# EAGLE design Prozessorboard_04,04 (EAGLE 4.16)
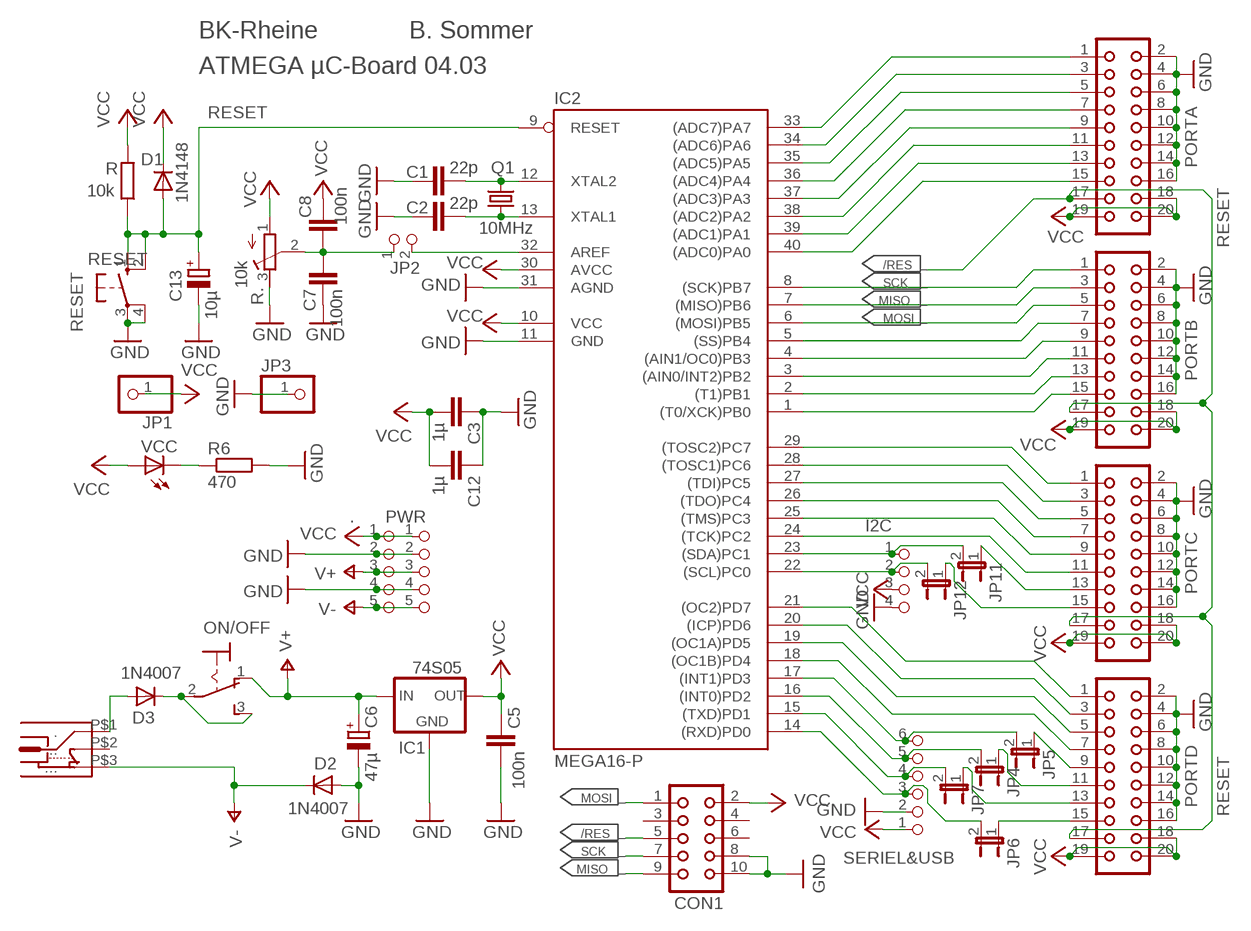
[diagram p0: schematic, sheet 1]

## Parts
.  PINHD-1X5  [1X05]
C1  22p  C-EU050-030X075  [C050-030X075]
C2  22p  C-EU050-030X075  [C050-030X075]
C3  1µ  C-EU025-030X050  [C025-030X050]
C5  100n  C-EU025-025X050  [C025-025X050]
C6  47µ  CPOL-EUE5-8.5  [E5-8,5]
C7  100n  C-EU025-030X050  [C025-030X050]
C8  100n  C-EU025-030X050  [C025-030X050]
C12  1µ  C-EU025-030X050  [C025-030X050]
C13  10µ  CPOL-EUE2.5-7  [E2,5-7]
CON1  CON10  [CON10]
D1  1N4148  DIODE-D-7.5  [D-7.5]
D2  1N4007  DIODE-D-7.5  [D-7.5]
D3  1N4007  DIODE-D-7.5  [D-7.5]
I2C  PINHD-1X4  [1X04]
IC1  74S05  78XXS  [78XXS]
IC2  MEGA16-P  [DIL40]
JP1  PINHD-1X1  [1X01]
JP2  PINHD-1X2  [1X02]
JP3  PINHD-1X1  [1X01]
JP4  JP1E  [JP1]
JP5  JP1E  [JP1]
JP6  JP1E  [JP1]
JP7  JP1E  [JP1]
JP11  JP1E  [JP1]
JP12  JP1E  [JP1]
ON/OFF  320-916  [320-916]
PORTA  CON20  [CON20]
PORTB  CON20  [CON20]
PORTC  CON20  [CON20]
PORTD  CON20  [CON20]
PWR  PINHD-1X5  [1X05]
Q1  10MHz  CRYTALHC49U70  [HC49U70]
R  10k  R-EU_0204/7  [0204/7]
R6  470  R-EU_0204/7  [0204/7]
R.  10k  R-TRIMM64Y  [RTRIM64Y]
RESET  10-XX  [B3F-10XX]
SERIEL&USB  PINHD-1X6  [1X06]
U$1  DC-CONNECTOR  [DC-CONNECTOR]
VCC  LED3MM  [LED3MM]

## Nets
AREF: IC2.32(AREF) JP2.2
AREF/P: C7.2 C8.1 JP2.1 R..2(S)
GND: ..2 ..4 C1.1 C2.1 C3.1 C5.1 C6.- C7.1 C12.1 C13.- CON1.8 CON1.10 D2.A I2C.4 IC1.GND IC2.11(GND) IC2.31(AGND) JP3.1 PORTA.2 PORTA.4 PORTA.6 PORTA.8 PORTA.10 PORTA.12 PORTA.14 PORTA.16 PORTB.2 PORTB.4 PORTB.6 PORTB.8 PORTB.10 PORTB.12 PORTB.14 PORTB.16 PORTC.2 PORTC.4 PORTC.6 PORTC.8 PORTC.10 PORTC.12 PORTC.14 PORTC.16 PORTD.2 PORTD.4 PORTD.6 PORTD.8 PORTD.10 PORTD.12 PORTD.14 PORTD.16 PWR.2 PWR.4 R6.2 R..3(A) RESET.3(P) RESET.4(P1) SERIEL&USB.2
N$2: D3.A U$1.P$1(.)
N$9: JP11.1 PORTC.13
N$16: R6.1 VCC.K(C)
N$21: I2C.2 IC2.22((SCL)PC0) JP12.2
N$23: D3.C ON/OFF.2(P) ON/OFF.3(S)
N$26: JP5.1 PORTD.9
N$27: JP4.1 PORTD.11
N$29: JP7.1 PORTD.13
N$30: JP6.1 PORTD.15
PA0: IC2.40((ADC0)PA0) PORTA.15
PA1: IC2.39((ADC1)PA1) PORTA.13
PA2: IC2.38((ADC2)PA2) PORTA.11
PA3: IC2.37((ADC3)PA3) PORTA.9
PA4: IC2.36((ADC4)PA4) PORTA.7
PA5: IC2.35((ADC5)PA5) PORTA.5
PA6: IC2.34((ADC6)PA6) PORTA.3
PA7: IC2.33((ADC7)PA7) PORTA.1
PB0: IC2.1((T0/XCK)PB0) PORTB.15
PB1: IC2.2((T1)PB1) PORTB.13
PB2: IC2.3((AIN0/INT2)PB2) PORTB.11
PB3: IC2.4((AIN1/OC0)PB3) PORTB.9
PB4: IC2.5((SS)PB4) PORTB.7
PB5(MOSI): CON1.1 IC2.6((MOSI)PB5) PORTB.5
PB6(MISO): CON1.9 IC2.7((MISO)PB6) PORTB.3
PB7(SCK): CON1.7 IC2.8((SCK)PB7) PORTB.1
PC0: JP12.1 PORTC.15
PC1: I2C.1 IC2.23((SDA)PC1) JP11.2
PC2: IC2.24((TCK)PC2) PORTC.11
PC3: IC2.25((TMS)PC3) PORTC.9
PC4: IC2.26((TDO)PC4) PORTC.7
PC5: IC2.27((TDI)PC5) PORTC.5
PC6: IC2.28((TOSC1)PC6) PORTC.3
PC7: IC2.29((TOSC2)PC7) PORTC.1
PD0(RXD): IC2.14((RXD)PD0) JP6.2 SERIEL&USB.3
PD1(TXD): IC2.15((TXD)PD1) JP7.2 SERIEL&USB.4
PD2(INT0): IC2.16((INT0)PD2) JP4.2 SERIEL&USB.5
PD3(INT1): IC2.17((INT1)PD3) JP5.2 SERIEL&USB.6
PD4: IC2.18((OC1B)PD4) PORTD.7
PD5: IC2.19((OC1A)PD5) PORTD.5
PD6: IC2.20((ICP)PD6) PORTD.3
PD7: IC2.21((OC2)PD7) PORTD.1
RESET: C13.+ CON1.5 D1.A IC2.9(RESET) PORTA.17 PORTB.17 PORTC.17 PORTD.17 R.1 RESET.1(S) RESET.2(S1)
V+: ..3 C6.+ IC1.IN ON/OFF.1(O) PWR.3
V-: ..5 D2.C PWR.5 U$1.P$3(...)
VCC: ..1 C3.2 C5.2 C8.2 C12.2 CON1.2 D1.C I2C.3 IC1.OUT IC2.10(VCC) IC2.30(AVCC) JP1.1 PORTA.18 PORTA.19 PORTA.20 PORTB.18 PORTB.19 PORTB.20 PORTC.18 PORTC.19 PORTC.20 PORTD.18 PORTD.19 PORTD.20 PWR.1 R.2 R..1(E) SERIEL&USB.1 VCC.A
XTAL1: C2.2 IC2.13(XTAL1) Q1.1
XTAL2: C1.2 IC2.12(XTAL2) Q1.2
Unconnected: CON1.3 CON1.4 CON1.6 U$1.P$2(..)

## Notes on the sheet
- BK-Rheine             B. Sommer
- ATMEGA µC-Board 04.03
- RESET
- RESET
- /RES
- SCK
- MISO
- MOSI
- RESET
- MOSI
- RESET
- /RES
- SCK
- MISO

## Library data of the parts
. PWR = pin-s:PINHD-1X5: PIN HEADER
C1-C3 C5 C7 C8 C12 = rcl:C-EU: CAPACITOR, European symbol
C6 = rcl:CPOL-EU: POLARIZED CAPACITOR, European symbol
C13 = rcl+:CPOL-EU: POLARIZED CAPACITOR, European symbol
CON1 = con-harting:CON10: CONNECTOR
D1-D3 = diode:DIODE-: DIODE
I2C = pinhead 02:PINHD-1X4: PIN HEADER
IC1 = v-reg:78XXS: VOLTAGE REGULATOR
IC2 = avr:MEGA16-P: MICROCONTROLLER 16 Kbytes FLASH 1 kbytes SRAM 512 bytes EEPROM USART 8-channel 10 bit ADC
JP1 JP3 = pinhead:PINHD-1X1: PIN HEADER
JP2 = pin-s:PINHD-1X2: PIN HEADER
JP4-JP7 JP11 JP12 = jumper:JP1E: JUMPER
ON/OFF = switch:320-916: TOGGLE SWITCH distributor RS Components
PORTA PORTB PORTC PORTD = con-harting:CON20: CONNECTOR
Q1 = crystal:CRYTAL: CRYSTAL
R R6 = rcl:R-EU_: RESISTOR, European symbol
R. = rcl:R-TRIMM: Trimm resistor
RESET = switch-omron:10-XX: OMRON SWITCH
SERIEL&USB = pinhead 02:PINHD-1X6: PIN HEADER
U$1 = DC-Conn:DC-CONNECTOR
VCC = led:LED: LED

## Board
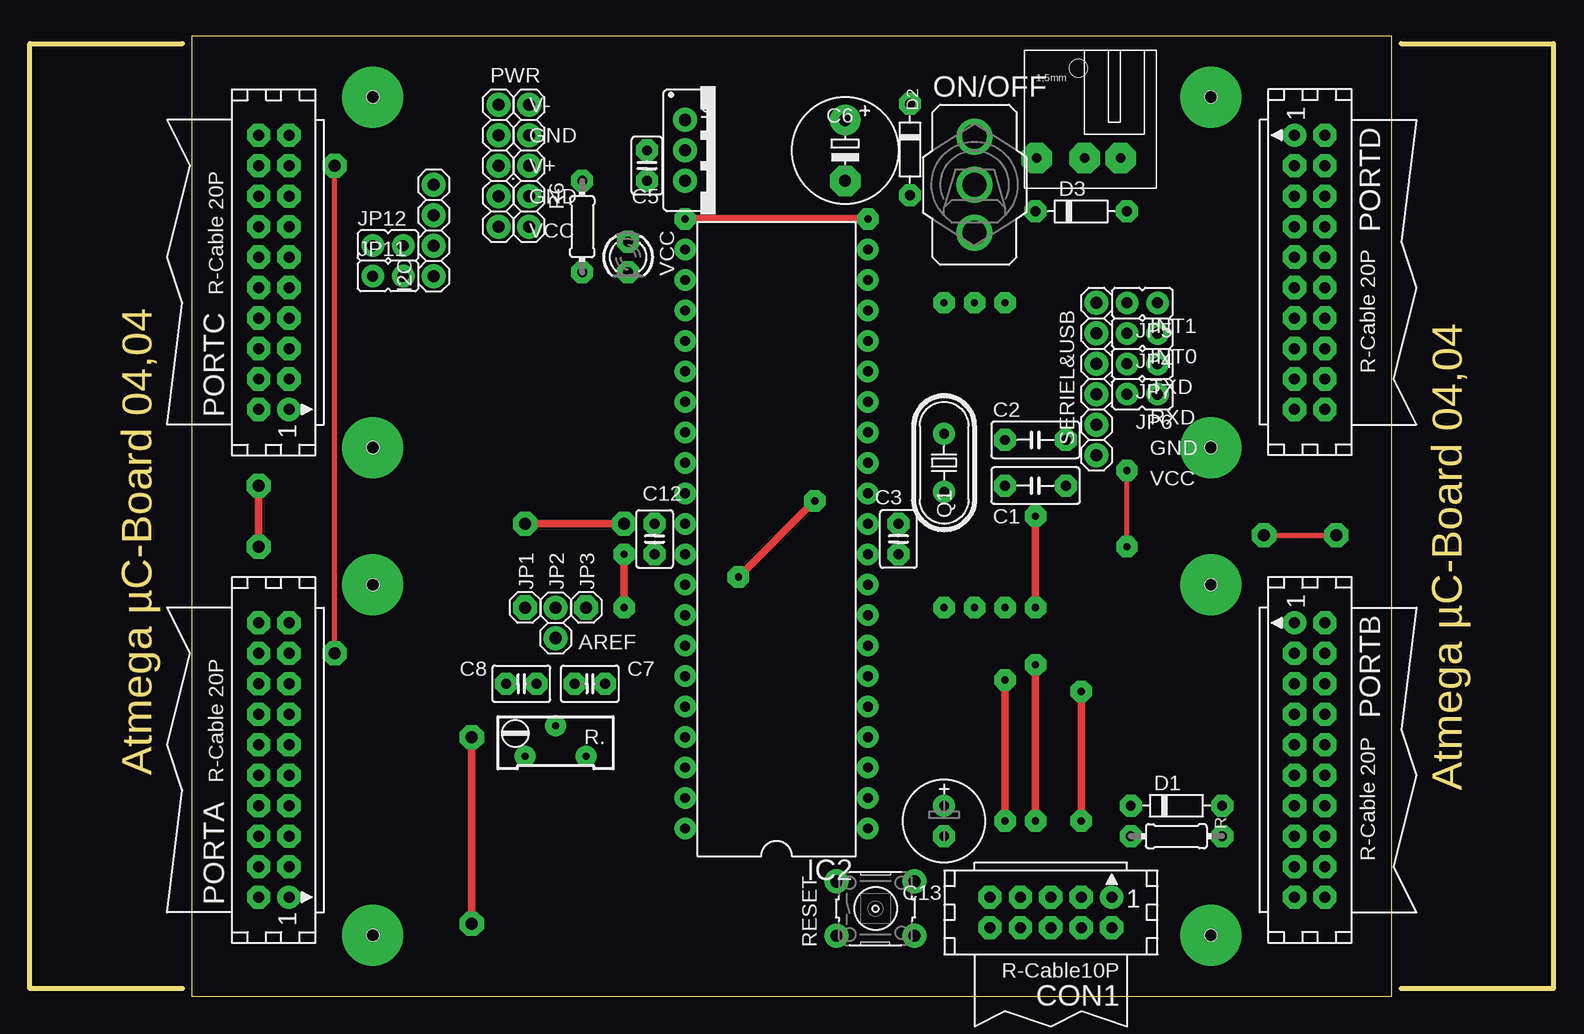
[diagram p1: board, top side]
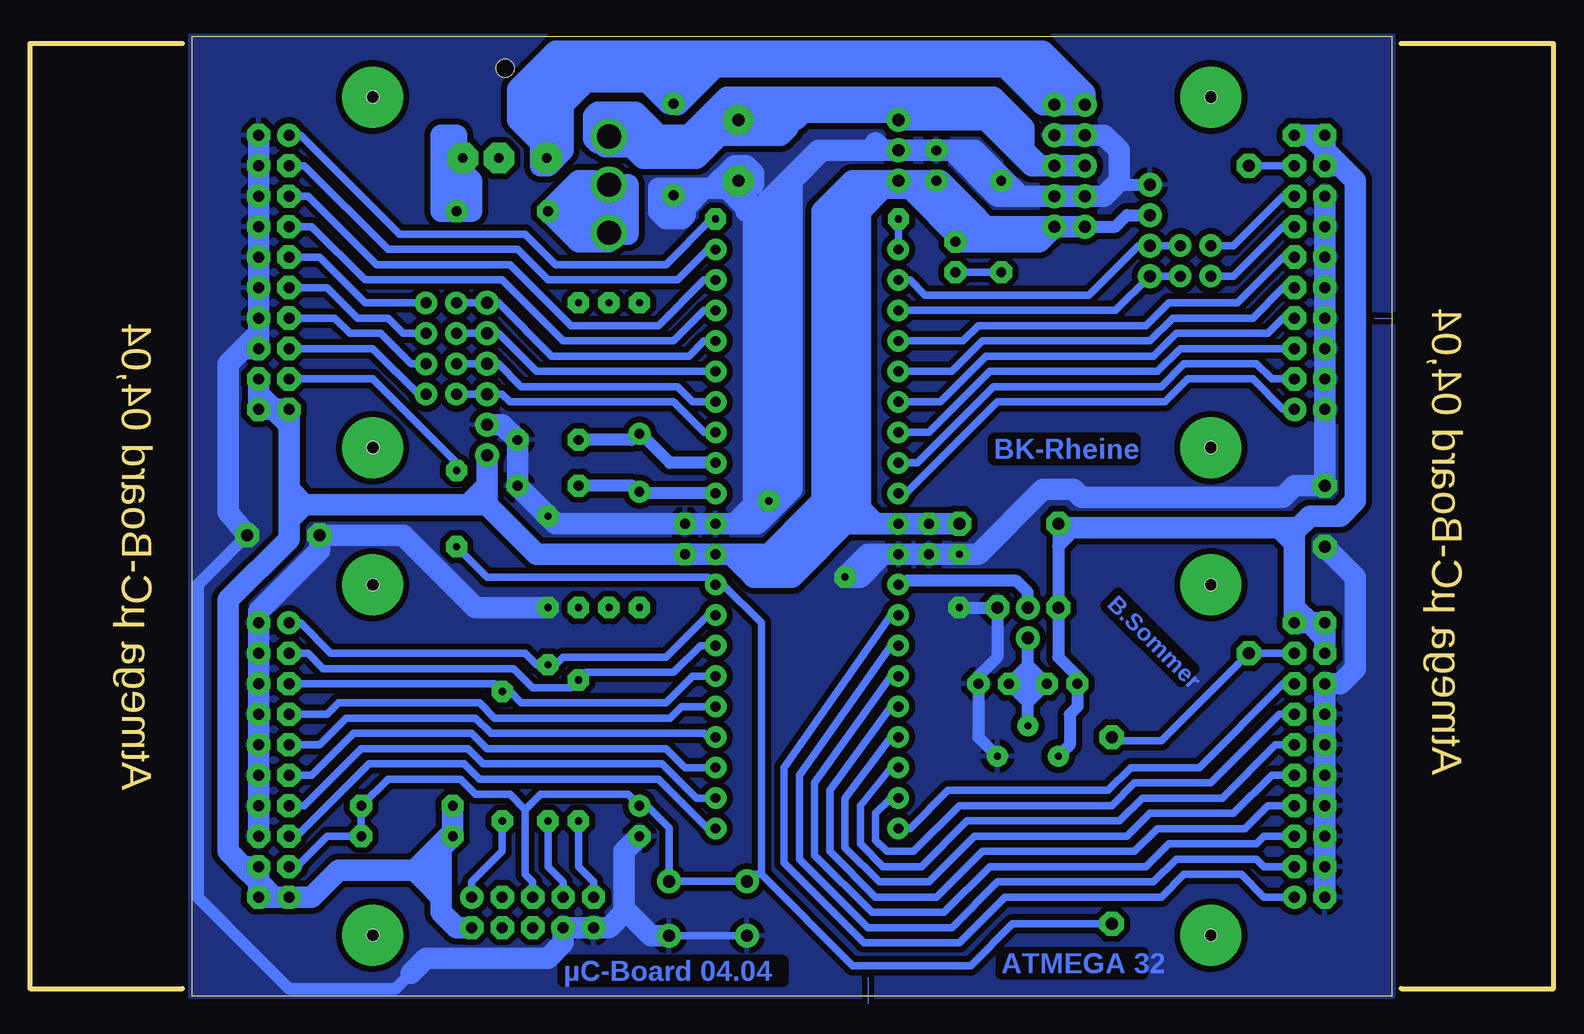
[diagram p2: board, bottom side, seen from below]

Size 127 x 80 mm. Coordinates in mm from the lower left corner, seen from the top.
Outline: 12.7,0.63 0,0.63 0,79.37 12.7,79.37
Outline: 114.3,79.37 127,79.37 127,0.63 114.3,0.63
Outline: 13.5,0 113.5,0 113.5,80 13.5,80 13.5,0
Copper layers (1*16): Top 0.035mm / dielectric 1.5mm / Bottom 0.035mm
Design rules "sommer_01": minimum track width 24mil, minimum drill 0.5mm, track to track 20mil, track to pad 23mil, pad to pad 20mil, via to via 20mil, smd to smd 8mil, copper to edge 0mil, drill to drill 8mil, minimum pad ring 20mil, minimum via ring 20mil, stop-mask expansion 4mil, vias tented up to drill 0mil, thermal gap 20mil
Holes 1 mm at 98.42,5.08 98.42,34.29 98.42,45.72 98.42,74.92 28.58,5.08 28.58,34.29 28.58,45.72 28.58,74.92

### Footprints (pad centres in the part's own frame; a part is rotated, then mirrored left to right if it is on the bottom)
1X05 = drill 1.016 long: 1 -5.08,0; 2 -2.54,0; 3 0,0; 4 2.54,0; 5 5.08,0
C050-030X075 = drill 0.813 pad 1.778 octagon: 1 -2.54,0; 2 2.54,0
C025-030X050 = drill 0.813 pad 1.778 octagon: 1 -1.27,0; 2 1.27,0
C025-025X050 = drill 0.813 pad 1.778 octagon: 1 -1.27,0; 2 1.27,0
E5-8,5 = drill 1.016 pad 2.54 round: + -2.54,0 | drill 1.016 pad 2.54 octagon: - 2.54,0
E2,5-7 = drill 0.813 pad 1.6 round: + -1.27,0 | drill 0.813 pad 1.6 octagon: - 1.27,0
CON10 = drill 0.914 round: 1 -5.08,-1.27 | drill 0.914 octagon: 2 -5.08,1.27; 3 -2.54,-1.27; 4 -2.54,1.27; 5 0,-1.27; 6 0,1.27; 7 2.54,-1.27; 8 2.54,1.27; 9 5.08,-1.27; 10 5.08,1.27
D-7.5 = drill 0.813 octagon: A 3.81,0; C -3.81,0
1X04 = drill 1.016 long: 1 -3.81,0; 2 -1.27,0; 3 1.27,0; 4 3.81,0
78XXS = drill 1.016 long: GND 0,-2.54; IN -2.54,-2.54; OUT 2.54,-2.54
DIL40 = drill 0.813 long: 1 -24.13,-7.62; 2 -21.59,-7.62; 3 -19.05,-7.62; 4 -16.51,-7.62; 5 -13.97,-7.62; 6 -11.43,-7.62; 7 -8.89,-7.62; 8 -6.35,-7.62; 9 -3.81,-7.62; 10 -1.27,-7.62; 11 1.27,-7.62; 12 3.81,-7.62; 13 6.35,-7.62; 14 8.89,-7.62; 15 11.43,-7.62; 16 13.97,-7.62; 17 16.51,-7.62; 18 19.05,-7.62; 19 21.59,-7.62; 20 24.13,-7.62; 21 24.13,7.62; 22 21.59,7.62; 23 19.05,7.62; 24 16.51,7.62; 25 13.97,7.62; 26 11.43,7.62; 27 8.89,7.62; 28 6.35,7.62; 29 3.81,7.62; 30 1.27,7.62; 31 -1.27,7.62; 32 -3.81,7.62; 33 -6.35,7.62; 34 -8.89,7.62; 35 -11.43,7.62; 36 -13.97,7.62; 37 -16.51,7.62; 38 -19.05,7.62; 39 -21.59,7.62; 40 -24.13,7.62
1X01 = drill 1.016 octagon: 1 0,0
1X02 = drill 1.016 long: 1 -1.27,0; 2 1.27,0
JP1 = drill 0.914 long: 1 0,-1.27; 2 0,1.27
320-916 = drill 2.007 long: 1 0,4.013; 2 0,0; 3 0,-4.013
CON20 = drill 0.914 round: 1 -11.43,-1.27 | drill 0.914 octagon: 2 -11.43,1.27; 3 -8.89,-1.27; 4 -8.89,1.27; 5 -6.35,-1.27; 6 -6.35,1.27; 7 -3.81,-1.27; 8 -3.81,1.27; 9 -1.27,-1.27; 10 -1.27,1.27; 11 1.27,-1.27; 12 1.27,1.27; 13 3.81,-1.27; 14 3.81,1.27; 15 6.35,-1.27; 16 6.35,1.27; 17 8.89,-1.27; 18 8.89,1.27; 19 11.43,-1.27; 20 11.43,1.27
HC49U70 = drill 0.813 round: 1 -2.413,0; 2 2.413,0
0204/7 = drill 0.813 pad 1.778 octagon: 1 -3.81,0; 2 3.81,0
RTRIM64Y = drill 0.61 pad 1.778 round: 1 0,-2.54; 2 -2.54,0; 3 0,2.54
B3F-10XX = drill 1.016 long: 1 -3.251,2.261; 2 3.251,2.261; 3 -3.251,-2.261; 4 3.251,-2.261
1X06 = drill 1.016 long: 1 -6.35,0; 2 -3.81,0; 3 -1.27,0; 4 1.27,0; 5 3.81,0; 6 6.35,0
DC-CONNECTOR = drill 0.8 pad 2.54 octagon: P$1 -2,7; P$2 1,7; P$3 5,7 | hole 1.5: 1.5,-0.5
LED3MM = drill 0.813 pad 1.778 octagon: A -1.27,0; K 1.27,0

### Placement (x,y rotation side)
.  39.05,69.21 90 top
C1  83.82,42.54 180 top
C2  83.82,46.35 180 top
C3  72.39,38.1 270 top
C5  51.44,69.21 270 top
C6  67.95,70.48 270 top
C7  46.67,26.03 180 top
C8  40.96,26.03 180 top
C12  52.07,38.1 90 top
C13  76.2,14.6 270 top
CON1  85.09,6.98 180 top
D1  95.57,15.87 0 top
D2  73.35,70.55 270 top
D3  87.63,65.4 0 top
I2C  33.66,63.81 90 top
IC1  57.15,70.48 270 top
IC2  62.23,38.1 90 top
JP1  41.27,32.38 270 top
JP2  43.81,31.11 90 top
JP3  46.35,32.38 270 top
JP4  92.71,55.24 90 top
JP5  92.71,57.78 90 top
JP6  92.71,50.16 90 top
JP7  92.71,52.7 90 top
JP11  29.84,60 270 top
JP12  29.84,62.54 270 top
ON/OFF  78.74,67.62 0 top
PORTA  20.32,19.68 90 top
PORTB  106.68,19.68 270 top
PORTC  20.32,60.32 90 top
PORTD  106.68,60.32 270 top
PWR  41.59,69.21 90 top
Q1  76.2,44.45 270 top
R  95.57,13.33 180 top
R6  46.04,64.13 90 top
R.  43.81,20 270 top
RESET  70.48,7.3 0 top
SERIEL&USB  88.9,51.43 90 top
U$1  88.9,76.83 180 top
VCC  49.85,61.59 270 top

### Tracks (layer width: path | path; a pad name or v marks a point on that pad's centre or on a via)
AREF
  Bottom 1.016: IC2.32 54.29,34.29 53.98,34.6 44.77,34.6 43.81,33.65 JP2.2
AREF/P
  Bottom 1.016: R..2 43.81,24.44 | 43.81,24.44 43.81,27.62 | 43.81,27.62 JP2.1 | C8.1 C7.2 | 43.81,24.44 C8.1 | 43.81,24.44 C7.2 | 43.81,27.62 C7.2 | 43.81,27.62 C8.1
GND  (via drill 0.6 pad 1.78, 0.61 pad 1.78, 1 pad 1.78)
  Top 0.406: v102.87,38.41 v108.9,38.41
  Top 0.61: v59.05,34.92 v65.41,41.27 | v19.05,37.46 v19.05,42.54 | v49.53,36.83 v49.53,32.38 | v83.82,40 v83.82,32.38
  Bottom 0.61: RESET.4 73.7,5.04 73.66,5.08 73.62,5.04 RESET.3
  Bottom 1.016: R..3 47.94,21.58 C7.1 47.94,26.66 46.35,28.25 JP3.1 v49.53,32.38 | 95.25,1.9 96.48,0.67 96.48,0.63 105.41,0.63 113.03,8.25 113.03,34.29 v108.9,38.41 | I2C.4 35.88,67.62 36.2,67.94
  Bottom 1.778: 55.88,36.83 IC2.31 C12.1 v49.53,36.83 47.94,36.83 42.55,42.22 40.01,42.22 39.37,41.59 22.54,41.59 21.59,42.54 v19.05,42.54 PORTC.2 PORTC.4 PORTC.6 PORTC.8 PORTC.10 PORTC.12 PORTC.14 PORTC.16 | 55.88,36.83 57.15,36.83 v59.05,34.92 57.78,34.92 55.88,36.83 | 68.26,39.37 67.31,39.37 66.67,40 | 68.26,39.37 IC2.11 C3.1 83.19,39.37 v83.82,40 C1.1 C2.1 87.63,47.62 SERIEL&USB.2 | v65.41,41.27 66.67,40 | 107.95,55.24 PORTD.16 109.22,53.97 | 107.95,55.24 PORTD.14 PORTD.12 PORTD.10 PORTD.8 PORTD.6 PORTD.4 PORTD.2 | PORTB.16 PORTB.14 PORTB.12 PORTB.10 PORTB.8 PORTB.6 PORTB.4 PORTB.2 107.95,32.06 102.87,37.14 v102.87,38.41 95.89,38.41 89.85,32.38 v83.82,32.38 | PORTA.2 PORTA.4 PORTA.6 PORTA.8 PORTA.10 PORTA.12 PORTA.14 PORTA.16 17.78,26.03 16.51,27.3 16.51,34.92 v19.05,37.46 | 109.22,53.97 110.49,52.7 110.49,40.32 v108.9,38.41 | 109.22,53.97 107.95,55.24 | 63.5,43.81 64.77,42.54 | 64.77,42.54 66.04,41.27 65.09,41.27 65.09,40.64 | 68.26,39.37 66.36,41.27 | 68.26,39.37 66.36,39.37 63.5,42.22 63.5,43.81 | RESET.4 75.21,5.04 77.47,7.3 | 77.47,7.3 77.47,12.06 C13.- | 77.47,7.3 77.47,6.98 78.74,5.71 CON1.10 CON1.8 82.55,4.44 83.82,3.17 93.98,3.17 95.25,1.9 | 41.27,66.67 ..2 37.47,66.67 36.2,67.94 36.2,70.48 37.47,71.75 ..4 PWR.4 | 41.27,66.67 PWR.2 | 44.45,66.67 44.77,66.67 R6.2 48.58,70.48 49.53,70.48 | 44.45,66.67 41.27,66.67 | 50.16,70.48 C5.1 IC1.GND 55.88,70.48 | 50.16,70.48 49.53,70.48 | 60.96,70.48 55.88,70.48 | 63.5,43.81 63.5,67.94 60.96,70.48 | 64.77,42.54 64.77,66.67 | 66.04,42.54 66.04,65.4 66.36,65.08 66.67,65.08 | 66.67,40 66.67,65.08 | 66.67,65.08 66.36,65.4 | 66.36,65.4 61.28,70.48 60.96,70.48
  Bottom 1.778: 67.95,67.3 67.95,66.99 66.36,65.4 | 67.95,67.3 C6.- 67.63,67.62 66.67,67.62 66.67,68.57 67.31,69.21 68.26,69.21 70.17,67.3 | 67.95,67.3 68.9,67.3 | 68.9,67.3 70.17,67.3 | 70.8,67.3 71.12,67.3 71.68,66.74 D2.A 73.35,66.68 73.34,66.67 73.34,67.3 | 70.17,67.3 70.8,67.3 | 70.8,67.3 74.61,67.3 74.61,65.4 73.98,64.77 72.71,64.77 72.39,65.08 72.39,65.72 | 72.39,65.72 73.34,65.72 | 70.8,67.3 72.39,65.72 | 67.31,65.4 67.31,65.72 68.9,67.3 | 55.88,70.48 56.52,71.11 | 49.53,70.48 45.72,66.67 44.45,66.67 | 44.45,66.67 46.35,66.67 50.16,70.48 | 50.16,70.48 48.26,70.48 44.45,66.67
  pour Bottom: 13.34,80 113.66,80 113.66,-0.01 13.34,-0.01
N$2
  Bottom 1.778: 90.17,65.4 D3.A 92.71,65.4 92.71,70.48 | 92.71,70.48 91.44,70.48 91.44,69.21 | 91.44,69.21 91.44,66.67 90.17,65.4 | 90.17,65.4 90.17,67.94 | U$1.P$1 90.9,68.67 90.17,67.94 | 92.71,70.48 92.71,71.75 91.44,71.75 91.44,69.21 | 90.17,67.94 91.44,69.21
N$4
  Bottom 0: 57.15,1.58 57.15,-0.64
N$5  (via drill 0.6 pad 1.78)
  other vias: 81.28,32.38
N$6  (via drill 0.6 pad 1.78)
  other vias: 78.74,32.38
N$7  (via drill 0.6 pad 1.78)
  other vias: 76.2,32.38
N$8  (via drill 0.6 pad 5.08)
  other vias: 28.58,74.92
N$9
  Bottom 0.61: PORTC.13 22.54,64.13 26.67,60 JP11.1
N$10  (via drill 0.6 pad 1.78)
  other vias: 81.28,57.78
N$11  (via drill 0.6 pad 5.08)
  other vias: 28.58,45.72
N$12  (via drill 0.6 pad 5.08)
  other vias: 28.58,34.29
N$13  (via drill 0.6 pad 5.08)
  other vias: 98.42,45.72
N$14  (via drill 0.6 pad 5.08)
  other vias: 98.42,74.92
N$15  (via drill 0.6 pad 5.08)
  other vias: 98.42,34.29
N$16
  Bottom 0.61: R6.1 VCC.K
N$17  (via drill 0.6 pad 5.08)
  other vias: 98.42,5.08
N$18  (via drill 0.6 pad 5.08)
  other vias: 28.58,5.08
N$19
  Bottom 0: 14.92,56.51 13.34,56.51
N$20
  pour Bottom: 13.97,78.1 15.24,79.37 111.76,79.37 113.03,78.1 113.03,1.9 111.76,0.63 15.24,0.63 13.97,1.9
N$21
  Bottom 0.61: IC2.22 53.66,59.69 52.39,58.41 38.73,58.41 34.61,62.54 I2C.2 JP12.2
N$22  (via drill 0.6 pad 1.78)
  other vias: 78.74,57.78
N$23
  Bottom 1.778: ON/OFF.2 77.15,67.62 77.15,63.5 78.74,63.5 ON/OFF.3 | 81.28,67.94 D3.C | 81.28,62.86 81.28,67.94 | 81.28,62.86 D3.C | D3.C 78.74,65.4 81.28,67.94 | 81.28,67.94 80.01,67.94 80.01,64.13 81.28,62.86 | 81.28,62.86 78.74,62.86 ON/OFF.2 | ON/OFF.2 78.74,67.94
N$26
  Bottom 0.61: PORTD.9 102.87,61.59 99.06,57.78 JP5.1
N$27
  Bottom 0.61: PORTD.11 102.23,59.05 99.69,56.51 97.16,56.51 95.89,55.24 JP4.1
N$28  (via drill 0.6 pad 1.78)
  other vias: 76.2,57.78
N$29
  Bottom 0.61: PORTD.13 101.6,56.51 100.33,55.24 97.79,55.24 95.25,52.7 JP7.1
N$30
  Bottom 0.61: PORTD.15 98.42,53.97 94.61,50.16 JP6.1
PA0
  Bottom 0.61: IC2.40 53.66,13.97 50.48,17.14 37.15,17.14 35.24,19.04 29.53,19.04 22.54,26.03 PORTA.15
PA1
  Bottom 0.61: IC2.39 55.24,16.5 56.52,15.24 56.52,13.01 55.56,12.06 53.34,12.06 49.53,15.87 36.83,15.87 34.92,17.77 28.58,17.77 22.86,23.49 PORTA.13
PA2
  Bottom 0.61: IC2.38 55.24,19.04 57.78,15.87 57.78,12.7 55.88,10.79 52.7,10.79 48.89,14.6 36.2,14.6 34.29,16.5 27.62,16.5 23.18,20.95 PORTA.11
PA3
  Bottom 0.61: IC2.37 55.24,21.58 59.05,16.5 59.05,12.38 56.2,9.52 52.07,9.52 48.26,13.33 35.56,13.33 33.66,15.24 26.67,15.24 23.5,18.41 PORTA.9
PA4
  Bottom 0.61: IC2.36 55.24,24.12 60.32,17.14 60.32,12.06 56.52,8.25 51.44,8.25 47.62,12.06 34.92,12.06 33.02,13.97 25.72,13.97 23.81,15.87 PORTA.7
PA5
  Bottom 0.61: IC2.35 55.24,26.66 61.59,17.77 61.59,11.74 56.83,6.98 50.8,6.98 46.99,10.79 33.97,10.79 32.07,12.7 24.77,12.7 24.13,13.33 PORTA.5
PA6
  Bottom 0.61: IC2.34 55.24,29.2 62.87,18.41 62.87,11.43 57.15,5.71 50.16,5.71 46.35,9.52 33.34,9.52 31.43,11.43 24.77,11.43 24.13,10.79 PORTA.3
PA7
  Bottom 0.61: IC2.33 55.24,31.74 64.14,19.04 64.14,11.11 57.47,4.44 49.53,4.44 45.72,8.25 32.7,8.25 30.8,10.16 26.04,10.16 24.13,8.25 PORTA.1
PB0
  Bottom 0.61: PORTB.15 104.78,13.33 98.74,19.36 90.8,19.36 89.53,18.09 74.61,18.09 70.48,13.97 IC2.1
PB1
  Bottom 0.61: PORTB.13 104.14,15.87 99.38,20.63 90.49,20.63 89.22,19.36 74.3,19.36 71.44,16.5 IC2.2
PB2
  Bottom 0.61: PORTB.11 103.5,18.41 100.01,21.9 90.17,21.9 88.9,20.63 73.98,20.63 72.39,19.04 IC2.3
PB3
  Bottom 0.61: PORTB.9 102.87,20.95 100.65,23.17 89.85,23.17 88.58,21.9 70.8,21.9 70.48,21.58 IC2.4
PB4
  Bottom 0.61: PORTB.7 102.23,23.49 101.28,24.44 89.53,24.44 88.27,23.17 73.66,23.17 72.71,24.12 IC2.5
PB5(MOSI)  (via drill 0.6 pad 1.78)
  Top 0.61: v87.63,25.39 v87.63,14.6
  Bottom 0.61: IC2.6 71.75,26.66 73.98,24.44 86.04,24.44 87,25.39 v87.63,25.39 88.27,26.03 PORTB.5 | CON1.1 90.17,9.52 87.63,12.06 v87.63,14.6
PB6(MISO)  (via drill 0.6 pad 1.78)
  Top 0.61: v81.28,14.6 v81.28,26.35
  Bottom 0.61: PORTB.3 103.82,28.57 102.55,27.3 86.68,27.3 85.09,25.71 81.91,25.71 v81.28,26.35 80.64,26.98 73.34,26.98 71.12,29.2 IC2.7 69.53,29.2 | CON1.9 80.01,9.52 81.28,10.79 v81.28,14.6
PB7(SCK)  (via drill 0.6 pad 1.78)
  Top 0.61: v83.82,14.6 v83.82,27.62
  Bottom 0.61: PORTB.1 104.46,31.11 101.92,28.57 85.72,28.57 84.77,27.62 v83.82,27.62 83.19,27.62 82.55,28.25 73.98,28.25 70.48,31.74 IC2.8 | CON1.7 82.55,9.52 83.82,10.79 v83.82,14.6
PC0
  Bottom 0.61: PORTC.15 22.54,66.67 26.67,62.54 JP12.1
PC1
  Bottom 0.61: IC2.23 36.51,57.15 I2C.1 JP11.2
PC2
  Bottom 0.61: IC2.24 49.21,54.61 47.94,55.88 33.97,55.88 32.07,57.78 26.35,57.78 22.54,61.59 PORTC.11
PC3
  Bottom 0.61: IC2.25 50.16,52.07 47.62,54.61 33.66,54.61 31.75,56.51 25.08,56.51 22.54,59.05 PORTC.9
PC4
  Bottom 0.61: IC2.26 51.12,49.53 47.31,53.34 33.34,53.34 31.43,55.24 23.81,55.24 22.54,56.51 PORTC.7
PC5
  Bottom 0.61: IC2.27 52.07,46.98 46.99,52.07 33.02,52.07 31.12,53.97 PORTC.5
PC6
  Bottom 0.61: IC2.28 53.02,44.45 46.67,50.8 32.7,50.8 30.8,52.7 24.77,52.7 23.5,51.43 PORTC.3
PC7
  Bottom 0.61: IC2.29 53.98,41.91 46.35,49.53 32.38,49.53 30.48,51.43 25.08,51.43 22.54,48.89 PORTC.1
PD0(RXD)
  Bottom 0.61: IC2.14 70.8,46.98 73.34,49.53 87,49.53 87.63,50.16 SERIEL&USB.3 JP6.2
PD1(TXD)
  Bottom 0.61: IC2.15 71.75,49.53 73.03,50.8 86.04,50.8 87.95,52.7 SERIEL&USB.4 JP7.2
PD2(INT0)
  Bottom 0.61: IC2.16 84.77,52.07 87.95,55.24 SERIEL&USB.5 JP4.2
PD3(INT1)
  Bottom 0.61: IC2.17 70.8,54.61 72.07,53.34 83.5,53.34 87.95,57.78 SERIEL&USB.6 JP5.2
PD4
  Bottom 0.61: IC2.18 70.8,57.15 73.34,54.61 82.55,54.61 87.63,59.69 99.06,59.69 103.5,64.13 PORTD.7
PD5
  Bottom 0.61: IC2.19 70.8,59.69 74.61,55.88 81.91,55.88 87,60.96 98.11,60.96 103.82,66.67 PORTD.5
PD6
  Bottom 0.61: IC2.20 70.48,62.23 73.03,59.69 83.82,59.69 86.36,62.23 97.16,62.23 104.14,69.21 PORTD.3
PD7  (via drill 0.6 pad 1.78)
  Top 0.61: v54.61,64.77 v69.85,64.77
  Bottom 0.61: IC2.21 v54.61,64.77 | PORTD.1 104.46,71.75 96.2,63.5 85.72,63.5 83.19,60.96 73.98,60.96 70.17,64.77 v69.85,64.77
RESET  (via drill 0.6 pad 1.78, 1 pad 1.78)
  Top 0.406: v91.44,37.46 v91.44,43.81 | v25.4,28.57 v25.4,69.21
  Top 0.61: v36.83,6.03 v36.83,21.58
  Bottom 0.61: PORTA.17 v25.4,28.57 32.7,21.27 35.88,21.27 36.2,21.58 v36.83,21.58 | 66.04,10.16 58.42,2.54 48.58,2.54 45.09,6.03 v36.83,6.03 | 66.04,10.16 66.04,31.11 69.22,34.29 IC2.9 70.48,34.92 88.9,34.92 v91.44,37.46 | 66.04,10.16 66.64,10.16 RESET.1 73.62,9.56 73.66,9.52 73.7,9.56 RESET.2 73.74,14.04 75.56,15.87 C13.+ 77.15,16.82 84.45,16.82 85.72,15.55 | 85.72,15.55 85.72,10.16 85.09,9.52 CON1.5 | 85.72,15.55 87,16.82 89.85,16.82 91.12,18.09 97.16,18.09 D1.A R.1 102.23,13.33 104.78,10.79 | v91.44,43.81 91.44,44.45 98.42,51.43 PORTD.17 | v25.4,69.21 PORTC.17
  Bottom 1.016: 104.78,10.79 PORTB.17
V+
  Bottom 1.778: ..3 PWR.3 42.86,69.21 | 42.86,69.21 43.5,69.21 47.31,73.02 IC1.IN 54.61,73.66 | 54.61,73.66 54.61,74.29 47.94,74.29 44.13,70.48 | 42.86,69.21 44.13,70.48 | 44.13,70.48 44.13,72.38 46.67,74.92 62.23,74.92 | 54.61,73.66 62.55,73.66 | 62.55,73.66 67.31,73.66 C6.+ | ON/OFF.1 77.36,71.64 76.2,70.48 71.12,70.48 68.58,73.02 C6.+ | C6.+ 63.18,73.02 62.55,73.66 | 62.55,73.66 62.55,74.61 62.23,74.92 | 62.23,74.92 68.9,74.92 72.07,71.75 | 72.07,71.75 72.39,71.43 72.39,71.75 74.61,71.75 | 74.61,71.75 76.2,71.75 77.15,72.7 79.69,72.7 79.69,72.07 80.01,71.75 80.01,71.43 | 80.01,71.43 79.69,71.11 79.38,71.11 79.06,70.8 76.84,70.8 75.88,69.84 71.44,69.84 69.53,71.75 64.45,71.75 63.82,72.38 | 80.01,71.43 80.01,73.02 | 80.01,71.43 80.01,73.34 79.69,73.66 76.52,73.66 74.61,71.75 | 72.07,71.75 74.61,71.75
V-
  Bottom 1.778: 39.05,75.24 39.69,75.88 41.91,75.88 44.77,78.73 70.48,78.73 | 70.48,78.73 73.34,75.88 73.34,76.19 74.93,77.78 82.87,77.78 82.87,78.42 | 71.75,78.73 83.19,78.73 | 71.75,78.73 73.66,76.83 80.01,76.83 82.55,74.29 | 39.05,75.24 ..5 PWR.5 42.55,74.29 45.72,77.46 69.85,77.46 73.03,74.29 73.1,74.36 D2.C 73.73,74.36 75.56,76.19 81.91,76.19 82.55,75.56 82.55,74.29 | 39.05,75.24 42.55,78.73 44.45,78.73 | 70.48,78.73 71.75,78.73 | 83.19,78.73 83.19,76.83 | U$1.P$3 84.12,69.83 84.14,69.84 82.55,71.43 82.55,71.75 | 82.55,74.29 82.55,71.75 | 82.55,71.75 82.55,70.48 83.82,69.21 84.45,69.21 84.45,71.11 86.36,73.02 86.36,75.56 85.09,76.83 | 83.19,78.73 85.09,76.83 | 83.19,78.73 83.19,72.38 83.82,71.75 85.09,73.02 85.09,76.83 | 85.09,76.83 83.82,76.83 83.82,73.02
VCC  (via drill 1 pad 1.78)
  Top 0.61: v41.27,39.37 v49.53,39.37
  Bottom 0.61: 49.21,62.86 VCC.A
  Bottom 1.016: R..1 40.32,20.95 40.32,23.49 39.69,24.12 C8.2 39.69,26.66 41.27,28.25 JP1.1 41.27,37.46 | v41.27,39.37 41.27,37.46 | 41.27,37.46 40.32,38.41 | ..1 36.51,64.13 35.56,65.08 I2C.3
  Bottom 1.778: 68.58,36.83 IC2.10 C3.2 84.77,36.83 88.9,40.95 | 63.5,36.83 68.58,36.83 | 60.96,39.37 63.5,36.83 | 56.52,39.37 IC2.30 C12.2 v49.53,39.37 | 56.52,39.37 59.05,39.37 | 63.5,36.83 64.77,35.55 67.31,35.55 | 68.58,36.83 67.31,35.55 | 106.68,8.25 PORTB.20 107.95,9.52 | 106.68,8.25 PORTB.19 103.5,8.25 101.28,10.47 94.93,10.47 | 107.95,9.52 PORTB.18 109.22,10.79 | 107.95,50.16 PORTD.20 106.68,48.89 | 107.95,50.16 PORTD.18 | 106.68,48.89 PORTD.19 105.41,47.62 | PORTA.18 19.05,29.84 | 19.05,29.84 PORTA.20 20.32,31.11 | 20.32,31.11 PORTA.19 21.59,32.38 | 21.59,32.38 21.59,37.78 | 21.59,37.78 21.59,38.73 | 21.59,38.73 21.59,39.05 22.86,39.05 | 22.86,39.05 40.96,39.05 v41.27,39.37 | 20.32,31.11 21.59,32.38 | 19.05,29.84 20.32,31.11 | 19.05,70.48 PORTC.18 17.78,69.21 | 19.05,70.48 PORTC.20 20.32,71.75 | 20.32,71.75 PORTC.19 | 19.05,70.48 20.32,71.75 | 17.78,69.21 16.51,67.94 16.51,41.27 17.78,40 20.32,40 21.59,38.73 | 21.59,37.78 22.86,39.05 | 109.22,10.79 110.49,12.06 110.49,33.02 105.41,38.1 105.41,39.68 | 106.68,48.89 107.95,50.16 | 105.41,47.62 106.68,48.89 | 109.22,10.79 107.95,9.52 | 107.95,9.52 106.68,8.25 | 17.78,69.21 19.05,70.48 | 56.52,39.37 57.78,40.64 57.78,65.4 | 60.96,39.37 60.96,41.27 | 59.05,39.37 60.96,39.37 | 59.05,39.37 59.37,39.68 59.37,66.03 | 60.96,41.27 66.04,36.19 | 58.42,40 63.5,34.92 66.67,34.92 67.31,35.55 | 105.41,40.95 105.41,39.68 | 105.41,40.95 105.41,42.22 | 105.41,42.22 105.41,47.62 | CON1.2 91.44,5.71 92.71,6.98 92.71,8.25 | 91.76,13.65 R.2 92.71,12.38 92.71,10.79 | 91.76,13.65 D1.C | 92.71,8.25 92.71,10.79 | 94.93,10.47 93.98,9.52 | 93.98,9.52 92.71,8.25 | 93.98,9.52 92.71,10.79 | 90.49,40.95 104.14,40.95
  Bottom 1.778: 104.14,40.95 105.41,40.95 | 60.96,41.27 60.96,65.4 | PWR.1 ..1 | 48.58,65.4 51.44,65.4 50.16,64.13 | 48.58,65.4 47.31,64.13 | PWR.1 42.23,63.5 45.4,63.5 | 45.4,63.5 44.13,63.5 44.45,63.81 | 49.53,63.5 45.4,63.5 | 49.53,63.5 50.16,64.13 | 50.16,64.13 47.31,64.13 | PWR.1 47.31,64.13 | PWR.1 42.86,62.86 46.99,62.86 | 48.26,62.86 48.89,62.86 49.53,63.5 | 48.26,62.86 46.99,62.86 | 51.12,67.94 48.58,65.4 | 57.78,65.4 55.88,67.3 53.66,67.3 49.21,62.86 48.26,62.86 | 51.12,67.94 C5.2 | 52.07,67.94 IC1.OUT 57.15,67.94 | 52.07,67.94 51.12,67.94 | 57.15,67.94 58.42,67.94 60.96,65.4 | 57.78,65.4 59.69,65.4 | 59.69,65.4 60.96,65.4 | 59.69,65.4 57.15,67.94 | 94.93,10.47 91.76,13.65 | 88.9,40.95 88.9,42.54 | 88.9,42.54 SERIEL&USB.1 | 88.9,40.95 90.49,40.95 | 88.9,42.54 90.49,40.95 | 52.07,67.94 46.99,62.86 | 104.14,40.95 105.41,42.22 | 104.14,40.95 105.41,39.68
XTAL1
  Bottom 1.016: C2.2 76.84,46.35 76.2,46.98 | 76.2,46.98 Q1.1 | IC2.13 73.66,44.45 76.2,46.98
XTAL2
  Bottom 1.016: 76.2,41.91 Q1.2 | C1.2 76.84,42.54 76.2,41.91 | IC2.12 76.2,41.91

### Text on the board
Bottom: BK-Rheine | B.Sommer | ATMEGA 32 | µC-Board 04.04
Dimension: Atmega µC-Board 04,04 | Atmega µC-Board 04,04
tNames: V- | GND | V+ | GND | VCC | INT1 | INT0 | TXD | RXD | GND | VCC | AREF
